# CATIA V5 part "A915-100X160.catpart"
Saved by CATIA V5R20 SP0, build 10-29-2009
Part number: A915-100X160
Source: Unknown
Property "A": "0.000"
Property "ARTICLENO": "A915-100X160"
Property "BOMINFO": "A915-100X160"
Property "CODE": "A915-100X160"
Property "CREATOR": "CADENAS GmbH"
Property "D": "13.500"
Property "D1": "20.000"
Property "FORM": "B"
Property "L": "160.000"
Property "L1": "25.000"
Property "L2": "110.000"
Property "LINA": "A915-100X160"
Property "NB": "A915-100X160"
Property "NBSYN": "$CODE."
Property "NN": "A915"
Property "NT": "VDI 3357 Wear Plates, steel"
Property "SCREW": "M12x25"
Property "SUPPLIER": "CF"
Property "T": "13.000"
Property "W": "100.000"
Bounding box of the stored display mesh (mm): x 0 to 20, y 0 to 160, z -50 to 50
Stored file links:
  C:\Users\borellobunino\Desktop\3D X SITO CF\A915\GSB_OILLESS_G22501100160\CATIAV5\A915-100X160.catpart
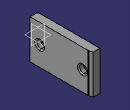
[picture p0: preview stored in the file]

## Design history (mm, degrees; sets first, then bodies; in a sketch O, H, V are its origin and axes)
Body1 "Geometry.1" (main body)
  Solid1 "A915-100X160.catpart": solid without history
